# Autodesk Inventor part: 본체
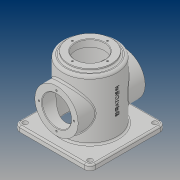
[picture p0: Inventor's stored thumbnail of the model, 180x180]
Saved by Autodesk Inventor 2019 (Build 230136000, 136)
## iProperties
Created: 2019-03
Part Number: 본체
Material: 일반
Document SubType Name: Modeling
Designer: PC312-17
Density: 1 g/cm^3
Appearance: 기본값
Mass: 414.383 g
Surface Area: 1156.45 cm^2
Volume: 414.383 cm^3
Author: PC312-17
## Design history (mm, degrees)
sketch "스케치1"
  geometry: C1 r 50 at (0, 0); 1 further point
  constraints: 1 centre point, 1 coincident
  dimensions: "d0" = 100 diameter of C1
extrude "돌출1" new body sketch "스케치1" distance "d1" = 120; taper "d2" = 0 deg
node "작업 평면1"
sketch "스케치4"
  geometry: C1 r 40 at (0, 60); 1 further point
  constraints: 1 centre point, 1 vertical alignment
  dimensions: "d10" = 80 diameter of C1; "d11" = 60 distance of point (0, 0) C1.centre
extrude "돌출4" join sketch "스케치4" stored distance "d12" = 112; taper "d13" = 0 deg
sketch "스케치5"
  geometry: C1 r 40 at (0, 0) reference; C2 r 27 at (0, 0); 1 further point
  constraints: 1 centre point, 1 coincident
  dimensions: "d14" = 54 diameter of C2
extrude "돌출5" cut sketch "스케치5" extent not by distance; stored distance "d15" = 112; taper "d16" = 0 deg
sketch "스케치6"
  geometry: L1 (70, 70)-(-70, 70); L2 (-70, 70)-(-70, -70); L3 (-70, -70)-(70, -70); L4 (70, -70)-(70, 70); L5 (70, 70)-(-70, -70); L6 (-70, 70)-(70, -70); C1 r 50 at (0, 0) reference; 1 further point
  constraints: 12 end point, 2 midpoint, 2 parallel, 1 horizontal, 1 perpendicular
  dimensions: "d17" = 140 distance of L3.end L2.end; "d18" = 140 distance of L2.end L1.end
extrude "돌출6" join sketch "스케치6" distance "d19" = 10; taper "d20" = 0 deg
sketch "스케치7"
  geometry: C1 r 27 at (0, 0) reference; C2 r 40 at (0, 0) reference; 2 further points
  constraints: 1 vertical alignment
  dimensions: "d21" = 32.5 distance of point (0, 32.5) C1.centre
hole "구멍1" sketch "스케치7" at (0, 32.5) diameter "d22" = 3.242; stored, may be unused: countersink angle "d26" = 90 deg, drill point angle "d28" = 118 deg; dims "d23" = 8, "d24" = 4, "d25" = 2, "d27" = 10
sketch "스케치8"
  geometry: C1 r 40 at (0, 0); 1 further point
  constraints: 1 centre point, 1 coincident
  dimensions: "d32" = 80 diameter of C1
extrude "돌출7" join sketch "스케치8" distance "d33" = 5; taper "d34" = 0 deg
sketch "스케치9"
  geometry: C1 r 27 at (0, 0); 1 further point
  constraints: 1 centre point, 1 coincident
  dimensions: "d35" = 54 diameter of C1
extrude "돌출8" cut sketch "스케치9" distance "d36" = 13; taper "d37" = 0 deg
sketch "스케치10"
  geometry: C1 r 45 at (0, 0); 1 further point
  constraints: 1 centre point, 1 coincident
  dimensions: "d38" = 90 diameter of C1
extrude "돌출9" cut sketch "스케치10" extent not by distance; stored distance "d39" = 13; taper "d40" = 0 deg
sketch "스케치11"
  geometry: 2 further points
  constraints: 1 vertical alignment
  dimensions: "d41" = 32.5 distance of point (0, 32.5) point (0, 0)
hole "구멍2" sketch "스케치11" at (0, 32.5) diameter "d42" = 3.242; stored, may be unused: countersink angle "d46" = 90 deg, drill point angle "d48" = 118 deg; dims "d43" = 8, "d44" = 4, "d45" = 2, "d47" = 10
fillet "모깎기1" dims "d52" = 10
sketch "스케치12"
  geometry: C1 r 4.5 at (60, 60); C2 r 4.5 at (-60, 60); C3 r 4.5 at (-60, -60); C4 r 4.5 at (60, -60); A1 r 10 centre (60, 60) between (70, 60) and (60, 70) reference; A2 r 10 centre (-60, 60) between (-60, 70) and (-70, 60) reference; A3 r 10 centre (-60, -60) between (-70, -60) and (-60, -70) reference; A4 r 10 centre (60, -60) between (60, -70) and (70, -60) reference; 1 further point
  constraints: 4 centre point, 4 coincident
  dimensions: "d53" = 9 diameter of C1; "d54" = 9 diameter of C2; "d55" = 9 diameter of C3; "d56" = 9 diameter of C4
extrude "돌출10" cut sketch "스케치12" distance "d57" = 13; taper "d58" = 0 deg
chamfer "모따기1" distance "d59" = 1; stored, may be unused: second distance "d60" = 2, angle "d61" = 45 deg
fillet "모깎기2" dims "d62" = 3
fillet "모깎기3" dims "d63" = 3
fillet "모깎기4" dims "d64" = 5
fillet "모깎기5" dims "d65" = 3
fillet "모깎기6" dims "d66" = 3
fillet "모깎기7" dims "d67" = 3
fillet "모깎기8" dims "d68" = 3
node "작업 평면2"
sketch "스케치14"
  geometry: L1 (0, -60)-(0, 60) reference; 3 further points
  constraints: 1 horizontal alignment, 1 midpoint, 1 other
  dimensions: "d70" = 70 distance of point (0, 0) point (70, 0)
feature "엠보싱1" sketch "스케치14" dims "d2" = 0, "d71" = 0.5, "d72" = 0
node "솔리드1"
mirror "미러1"
pattern_circular "원형 패턴1" dims angle "d30" = 360 deg
mirror "미러2"
pattern_circular "원형 패턴2" dims angle "d50" = 360 deg
node "투영된 루프1"
node "투영된 루프2"
other parameters: "d9" = 62
